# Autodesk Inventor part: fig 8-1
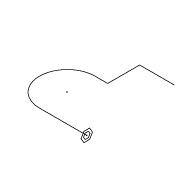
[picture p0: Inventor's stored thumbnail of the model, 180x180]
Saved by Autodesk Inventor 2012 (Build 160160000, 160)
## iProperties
Created: 2004-05
Part Number: fig 8-1
Document SubType Name: Modeling
Designer: CADCIM Technologies
Manufacturer: Standard
Standards Organization: Custom
Density: 1 g/cm^3
Material: Default
Author: CADCIM Technologies
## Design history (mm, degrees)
sketch "Sketch1"
  geometry: L1 (-42.583, 3.219)-(-90.066, 3.219); L2 (-90.066, 58.92)-(-77.282, 58.92); L3 (-77.282, 58.92)-(-77.282, 91.063); L4 (-77.282, 91.063)-(-42.583, 91.063); A1 r 27.851 centre (-90.066, 31.07) between (-90.066, 58.92) and (-90.066, 3.219)
  constraints: 8 end point, 2 parallel, 2 point on circle, 2 tangent, 1 centre point, 1 perpendicular
workplane "Work Plane2"
sketch "Sketch2"
  geometry: L1 (-5.697, 0)-(-2.849, 4.934); L2 (-2.849, 4.934)-(2.849, 4.934); L3 (2.849, 4.934)-(5.697, 0); L4 (5.697, 0)-(2.849, -4.934); L5 (2.849, -4.934)-(-2.849, -4.934); L6 (-2.849, -4.934)-(-5.697, 0); L7 (-3.256, 0)-(-1.628, 2.819); L8 (-1.628, 2.819)-(1.628, 2.819); L9 (1.628, 2.819)-(3.256, 0); L10 (3.256, 0)-(1.628, -2.819); L11 (1.628, -2.819)-(-1.628, -2.819); L12 (-1.628, -2.819)-(-3.256, 0); 2 further points
  constraints: 24 end point, 1 coincident, 22 other
